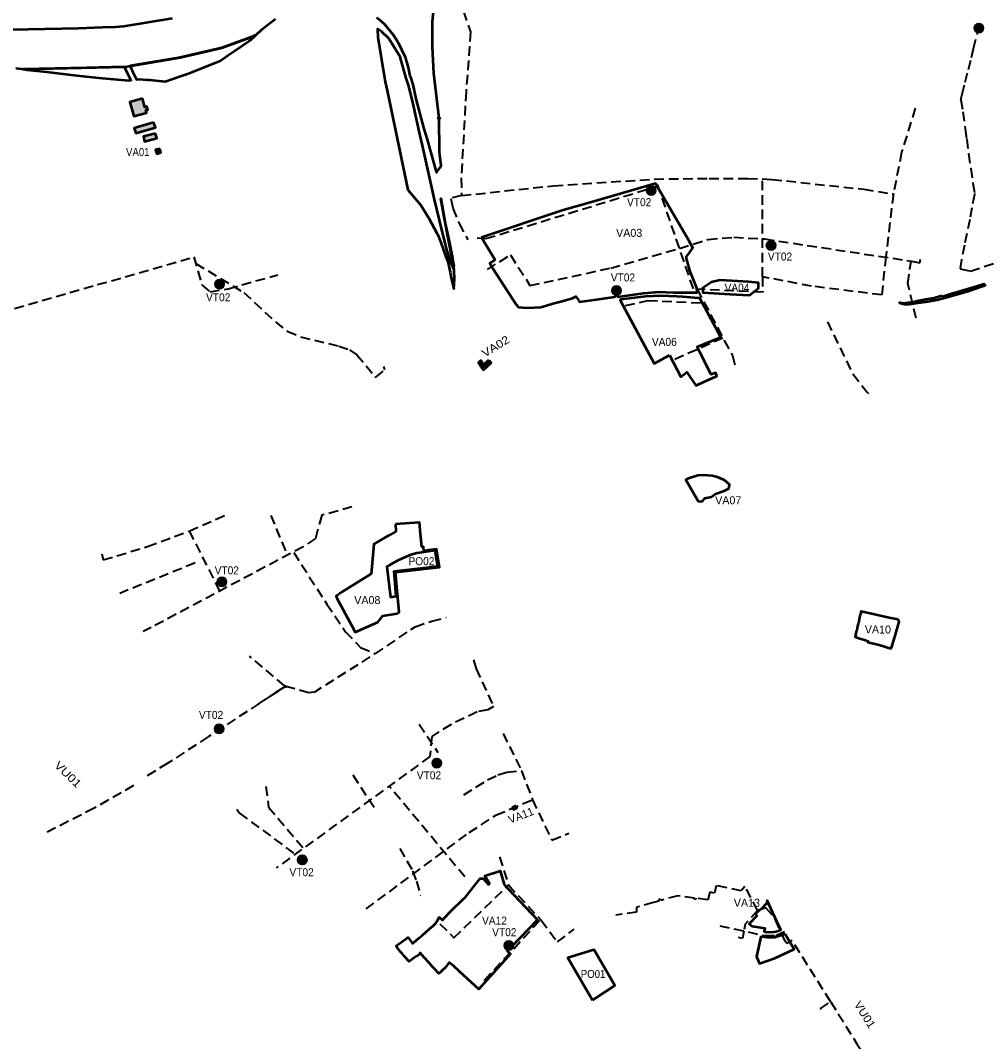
# Model space of a CAD drawing. Extents: x -650145 to -642675, y -1074338 to -1066724.
# Drawn here: x -648927 to -646512, y -1071699 to -1069147 of the extents above; entities that cross this region are included whole.
import ezdxf

# ---------------------------------------------------------------- set-up
doc = ezdxf.new("R2010")
doc.units = 0
doc.header["$LTSCALE"] = 8
doc.header["$PDMODE"] = 32
doc.header["$PDSIZE"] = 4
doc.linetypes.add('MEDIUM_DASHED', pattern=[4.5, 3, -1.5])
for name, color, linetype, lineweight in [('12', 7, 'MEDIUM_DASHED', 40), ('15', 7, 'Continuous', 13), ('44', 7, 'Continuous', 53), ('45', 7, 'Continuous', 53), ('46', 7, 'Continuous', 53), ('60', 7, 'Continuous', 53)]:
    doc.layers.add(name, color=color, linetype=linetype, lineweight=lineweight)
for name, color, linetype in [('17', 7, 'Continuous'), ('2', 7, 'Continuous'), ('3', 7, 'Continuous'), ('4', 7, 'Continuous'), ('5', 7, 'Continuous')]:
    doc.layers.add(name, color=color, linetype=linetype)

msp = doc.modelspace()

# ---------------------------------------------------------------- hatches: boundary and pattern name
at = {"layer": '15'}
for points in [[(-646519.621, -1069166.048, 1), (-646543.146, -1069166.048, 1)], [(-647338.289, -1069571.583, 1), (-647361.814, -1069571.583, 1)], [(-647038.994, -1069709.305, 1), (-647062.519, -1069709.305, 1)], [(-648416.978, -1069806.101, 1), (-648440.503, -1069806.101, 1)], [(-647425.058, -1069822.133, 1), (-647448.583, -1069822.133, 1)], [(-648411.342, -1070550.264, 1), (-648434.867, -1070550.264, 1)], [(-648418.374, -1070917.603, 1), (-648441.898, -1070917.603, 1)], [(-647874.426, -1071003.073, 1), (-647897.951, -1071003.073, 1)], [(-648210.363, -1071245, 1), (-648233.888, -1071245, 1)], [(-647694.212, -1071458.99, 1), (-647717.737, -1071458.99, 1)]]:
    msp.add_hatch(color=256, dxfattribs=at).paths.add_polyline_path(points)
at = {"layer": '60'}
for points in [[(-648621.37, -1069342.03), (-648652.93, -1069350.8), (-648642.85, -1069386.53), (-648611.53, -1069377.7), (-648613.3, -1069371.42), (-648608.07, -1069369.95), (-648610.3, -1069362.04), (-648615.51, -1069363.51)], [(-648593.77, -1069401.82), (-648642.06, -1069415.98), (-648638.41, -1069428.97), (-648589.26, -1069414.15), (-648592.11, -1069405.18)], [(-648589.16, -1069429.3), (-648619.35, -1069437.29), (-648616.15, -1069449.33), (-648585.96, -1069441.33)], [(-648578.5, -1069467.6), (-648588.59, -1069470.49), (-648585.91, -1069479.97), (-648575.76, -1069477.15)], [(-647753.96, -1069997.9), (-647755.37, -1069999.17), (-647757.35, -1069996.96), (-647768.87, -1070007.32), (-647775.67, -1069996.86), (-647781.47, -1070001.96), (-647774.7, -1070012.64), (-647775.34, -1070013.22), (-647769.35, -1070019.98), (-647749.87, -1070002.45)], [(-647687.68, -1071110.18), (-647696.64, -1071114.02), (-647694.63, -1071118.73), (-647685.66, -1071114.89)]]:
    msp.add_hatch(color=256, dxfattribs=at).paths.add_polyline_path(points)

# ---------------------------------------------------------------- linework, layer by layer
at = {"layer": '12'}
for p, q in [((-647072.241, -1069787.533), (-647072.241, -1069543.185)), ((-647291.307, -1069993.228), (-647170.84, -1069940.165)), ((-648300.887, -1070383.875), (-648259.756, -1070483.608)), ((-648504.855, -1070423.103), (-648428.725, -1070573.36)), ((-648490.212, -1070502.827), (-648678.059, -1070578.955)), ((-648332.818, -1070855.794), (-648263.929, -1070810.849)), ((-647929.7, -1070905.7), (-647883.483, -1070976.724)), ((-647720.463, -1070929.111), (-647674.039, -1071022.323)), ((-648042.555, -1071114.098), (-648099.428, -1071026.867)), ((-647815.949, -1071287.658), (-648004.905, -1071060.503)), ((-647767.223, -1071546.187), (-647626.359, -1071394.366))]:
    msp.add_line(p, q, dxfattribs=at)
for points in [[(-647819.537, -1069124.409), (-647801.818, -1069175.256), (-647812.644, -1069324.711), (-647825.015, -1069541.552), (-647823.978, -1069584.663), (-647594.109, -1069559.949), (-647342.265, -1069543.531), (-647205.182, -1069541.582), (-647108.806, -1069541.669), (-647047.983, -1069544.191), (-646818.857, -1069568.917), (-646744.903, -1069580.656), (-646763.998, -1069737.618), (-646773.775, -1069832.942), (-646949.668, -1069811.025), (-647072.241, -1069787.533), (-647071.353, -1069826.293), (-647244.785, -1069818.042), (-647338.767, -1069543.481)], [(-646576.25, -1069344.69), (-646576.07, -1069344.19), (-646572.92, -1069331.38), (-646565.43, -1069301.45), (-646557.53, -1069269.39), (-646550.09, -1069239.83), (-646544.34, -1069216.84), (-646534.934, -1069179.318)], [(-646576.25, -1069344.69), (-646576.14, -1069345.28), (-646571.6, -1069375.24), (-646565.13, -1069418.25), (-646561.67, -1069443.36), (-646557.02, -1069479.48), (-646551.76, -1069516.65), (-646546.19, -1069553.66), (-646542.189, -1069579.489), (-646541.86, -1069581.61), (-646548.99, -1069615.32), (-646554.11, -1069644.37), (-646561.65, -1069679.08), (-646567.03, -1069708.57), (-646575.01, -1069744.61), (-646578.22, -1069766.52), (-646578.238, -1069766.625), (-646578.433, -1069767.754), (-646552.777, -1069773.113), (-646552.12, -1069773.25), (-646464.51, -1069744.51)], [(-646690.349, -1069366.515), (-646724.478, -1069476.486), (-646744.903, -1069580.656)], [(-647785.07, -1069690.63), (-647763.238, -1069692.321), (-647332.905, -1069560.606)], [(-647823.978, -1069584.663), (-647851.235, -1069591.7), (-647845.629, -1069616.01), (-647830.41, -1069654.06), (-647808.595, -1069694.89)], [(-647279.5, -1069716.624), (-647208.318, -1069694.158), (-647143.504, -1069688.843), (-647066.866, -1069693.057), (-646699.975, -1069748.527), (-646678.869, -1069753.112), (-646676.91, -1069743.82)], [(-647759.613, -1069769.184), (-647701.982, -1069733.103), (-647653.087, -1069809.089), (-647451.321, -1069765.984), (-647279.5, -1069716.624)], [(-649044.908, -1069897.057), (-648493.206, -1069738.027), (-648473.126, -1069807.804), (-648452.457, -1069825.52), (-648407.58, -1069817.388), (-648283.564, -1069782.827)], [(-648488.496, -1069754.394), (-648368.286, -1069826.694), (-648289.499, -1069900.443), (-648259.719, -1069923.17), (-648226.806, -1069937.698), (-648130.85, -1069960.81), (-648103.867, -1069970.198), (-648085.696, -1069982.585), (-648038.819, -1070039.248), (-648015.643, -1070020.009), (-648018.277, -1070012.103)], [(-646687.702, -1069891.186), (-646709.186, -1069804.667), (-646700.4, -1069748.435)], [(-647235.467, -1069818.485), (-647167.428, -1069946.59), (-647147.296, -1069984.626), (-647140.3, -1070010.7)], [(-647414.535, -1069859.089), (-647358.559, -1069846.998), (-647217.195, -1069852.888)], [(-646909.766, -1069900.481), (-646846.095, -1070030.546), (-646811.614, -1070075.327), (-646807.189, -1070079.418)], [(-648723.27, -1070480.1), (-648719.781, -1070495.186), (-648608.642, -1070462.104), (-648504.855, -1070423.103), (-648414.278, -1070383.546)], [(-648097.961, -1070362.859), (-648173.666, -1070383.828), (-648189.212, -1070442.001), (-648219.63, -1070462.294), (-648600.13, -1070664.406), (-648620.205, -1070674.13)], [(-648243.287, -1070476.499), (-648161.107, -1070605.619), (-648114.121, -1070674.786), (-648076.532, -1070713.851), (-648039.863, -1070730.017), (-647940.305, -1070662.397), (-647898.38, -1070648.071), (-647862.25, -1070638.96)], [(-648053, -1070737.9), (-648191.415, -1070825.487), (-648206.369, -1070827.623), (-648259.779, -1070812.134), (-648269.723, -1070814.735), (-648457.192, -1070937.393), (-648558.532, -1071003.71), (-648610.798, -1071035.598)], [(-648259.67, -1070812.106), (-648266.577, -1070810.067), (-648354.282, -1070735.576)], [(-647794.16, -1070745.19), (-647787.83, -1070767.157), (-647743.987, -1070862.016), (-647758.284, -1070869.702), (-647784.836, -1070875.103), (-647850.393, -1070906.456), (-647898.698, -1070936.31), (-647903.521, -1070987.043), (-648287.54, -1071265.293)], [(-647818.707, -1071082.607), (-647759.543, -1071045.17), (-647733.735, -1071032.504), (-647710.774, -1071025.971), (-647674.039, -1071022.323), (-647646.98, -1071094.735)], [(-648643.705, -1071059.314), (-648742.207, -1071116.062), (-648865.074, -1071178.477)], [(-648313.283, -1071061.443), (-648306.336, -1071112.945), (-648219.799, -1071215.376)], [(-648062.403, -1071367.342), (-647805.426, -1071176.999), (-647738.219, -1071133.017), (-647646.98, -1071094.735), (-647598.326, -1071195.826), (-647556.251, -1071178.604)], [(-648386.1, -1071118.4), (-648378.803, -1071128.097), (-648240.257, -1071231.033)], [(-647978.731, -1071216.254), (-647946.561, -1071272.093), (-647936.852, -1071298.253), (-647926.931, -1071334.225)], [(-647728.988, -1071237.115), (-647707.004, -1071307.776), (-647625.351, -1071395.71), (-647584.501, -1071450.177), (-647542.285, -1071418.425)], [(-647878.3, -1071404.7), (-647843.135, -1071439.808), (-647707.004, -1071307.776)], [(-647125.34, -1071322.14), (-647187.77, -1071309.47), (-647192.05, -1071327.84), (-647204.02, -1071325.39), (-647208.89, -1071345.24), (-647238.16, -1071341.03), (-647238.54, -1071343.71), (-647242.66, -1071343.12), (-647242.27, -1071340.44), (-647283.52, -1071334.51), (-647326.47, -1071346.51), (-647327.32, -1071343.47), (-647332.03, -1071344.79), (-647331.18, -1071347.82), (-647344.33, -1071351.49)], [(-647084.37, -1071371.2), (-647115.91, -1071311.35), (-647125.34, -1071322.14)], [(-647344.33, -1071351.49), (-647386.85, -1071363.37), (-647386.8, -1071375.58), (-647438.34, -1071382.93)], [(-647084.37, -1071371.2), (-647115.19, -1071405.75), (-647117.79, -1071418.96)], [(-646901.7, -1071599.29), (-646997.62, -1071446.82), (-647011, -1071454.09), (-647015.17, -1071448), (-647045.84, -1071382.28), (-647050.73, -1071380.13), (-647063.41, -1071364.59), (-647084.37, -1071371.2)], [(-647178.442, -1071409.986), (-647065.935, -1071434.456), (-647038.805, -1071433.925), (-647016.651, -1071423.819)], [(-647118.63, -1071423.24), (-647122.21, -1071441.39), (-647132.07, -1071439.37)], [(-646925.38, -1071619.26), (-646926.8, -1071616.72), (-646901.7, -1071599.29)], [(-646901.7, -1071599.29), (-646836.01, -1071704.74), (-646804.94, -1071754.31)]]:
    msp.add_lwpolyline(points, dxfattribs=at)
at = {"layer": '15', "lineweight": 35}
for centre in [(-646531.383, -1069166.048), (-647350.051, -1069571.583), (-647050.756, -1069709.305), (-648428.74, -1069806.101), (-647436.82, -1069822.133), (-648423.104, -1070550.264), (-648430.136, -1070917.603), (-647886.188, -1071003.073), (-648222.125, -1071245), (-647705.974, -1071458.99)]:
    msp.add_circle(centre, 11.762, dxfattribs=at)
at = {"layer": '44'}
for p, q in [((-647862.266, -1069668.613), (-647843.449, -1069768.252)), ((-646729.54, -1069853.69), (-646729.24, -1069851.41))]:
    msp.add_line(p, q, dxfattribs=at)
for points in [[(-647893.553, -1069279.017), (-647896.67, -1069213.573), (-647896.362, -1069149.171), (-647886.615, -1069053.052)], [(-648036.291, -1069139.458), (-648031.92, -1069142.67), (-648016.36, -1069156.54), (-647993.8, -1069184.11)], [(-648526.15, -1069286.21), (-648508.95, -1069280.01), (-648427.08, -1069247.75), (-648407.73, -1069233.88), (-648389.91, -1069221.86), (-648355.81, -1069198.88), (-648351.77, -1069195.88), (-648338.523, -1069183.389), (-648354.978, -1069190.492)], [(-648005.47, -1069192.09), (-648024.02, -1069174.7), (-648034.421, -1069167.61)], [(-648034.421, -1069167.61), (-648034.421, -1069167.61), (-648033, -1069189), (-648015, -1069300), (-648010.092, -1069322.087), (-647980.331, -1069465.915), (-647958.34, -1069570.699), (-647925.99, -1069608.57), (-647906.16, -1069641.48), (-647885.665, -1069678.788), (-647885.663, -1069678.794), (-647883.51, -1069682.71), (-647875.82, -1069701.85), (-647875.82, -1069701.85), (-647864.19, -1069735.12), (-647858.44, -1069749.43), (-647852.63, -1069775.7), (-647850.66, -1069785.74), (-647849.165, -1069793.367)], [(-647993.8, -1069184.11), (-647982.58, -1069202.33), (-647965.06, -1069238.95), (-647957.56, -1069264.74), (-647953.01, -1069285.73), (-647951.841, -1069289.09)], [(-648354.978, -1069190.492), (-648423.173, -1069215.44), (-648527.693, -1069239.938), (-648652.716, -1069260.657), (-648647.059, -1069272.723), (-648636.85, -1069294.49), (-648630.82, -1069293.63), (-648609.425, -1069295.033), (-648603.228, -1069295.53), (-648565.18, -1069299.46), (-648526.15, -1069286.21)], [(-647962.2, -1069290.88), (-647974.81, -1069246.86), (-647977.29, -1069238.21), (-648005.47, -1069192.09)], [(-647880.318, -1069391.297), (-647880.326, -1069390.832), (-647893.553, -1069279.017)], [(-647852.78, -1069745.71), (-647859.722, -1069722.428), (-647872.87, -1069673.56), (-647892.79, -1069591.06), (-647892.789, -1069591.06), (-647893.75, -1069587.08), (-647922.04, -1069459.71), (-647925.16, -1069445.68), (-647928.41, -1069431.03), (-647945.28, -1069355.1), (-647956.27, -1069311.58), (-647962.2, -1069290.88)], [(-647951.841, -1069289.09), (-647945.63, -1069306.95), (-647938.77, -1069343.17), (-647918.08, -1069417.43), (-647909.67, -1069444.46), (-647889.22, -1069519.32), (-647887.087, -1069527.229), (-647885.782, -1069525.389), (-647882.551, -1069520.835), (-647878.73, -1069515.45)], [(-647878.73, -1069515.45), (-647874.75, -1069509.84), (-647878.93, -1069475.09), (-647880.318, -1069391.297)], [(-647843.449, -1069768.252), (-647844.371, -1069761.991), (-647842.438, -1069760.647), (-647845.086, -1069748.753), (-647846.484, -1069736.663), (-647855.158, -1069695.232), (-647865.69, -1069647.32), (-647876.061, -1069592.206), (-647862.266, -1069668.613)], [(-647841.402, -1069792.351), (-647842.489, -1069773.282), (-647842.622, -1069770.956), (-647843.337, -1069769.013), (-647843.443, -1069768.293), (-647852.78, -1069745.71)], [(-647849.165, -1069793.367), (-647843.74, -1069817.63), (-647841.402, -1069792.351)], [(-646515.63, -1069810.24), (-646522.32, -1069812.28), (-646560.92, -1069825.33), (-646613.65, -1069840.02), (-646620.06, -1069841.69), (-646629.83, -1069844.23), (-646635.93, -1069845.82), (-646658.5, -1069850.59), (-646689.73, -1069854.58), (-646705.87, -1069856.62), (-646717.66, -1069857.11), (-646729.54, -1069853.69)], [(-646593.34, -1069827.68), (-646518.19, -1069805.27), (-646515.63, -1069810.24)], [(-646729.24, -1069851.41), (-646723.5, -1069852.83), (-646719.82, -1069853.78), (-646689.63, -1069849.7), (-646689.8, -1069848.71), (-646664.22, -1069843.72), (-646648.18, -1069841.04), (-646648.28, -1069841.78), (-646638.34, -1069838.73), (-646623.31, -1069834.1)], [(-646623.31, -1069834.1), (-646622.54, -1069835.88), (-646622.19, -1069836.71), (-646597.29, -1069828.86), (-646593.34, -1069827.68)]]:
    msp.add_lwpolyline(points, dxfattribs=at)
msp.add_lwpolyline([(-648730.66, -1069290.43), (-648655.53, -1069297.18), (-648650.06, -1069296.39), (-648650.58, -1069295.34), (-648662.417, -1069271.858), (-648666.827, -1069262.738), (-648761.189, -1069265.035), (-648918.889, -1069268.875), (-648909.86, -1069270.02), (-648861.49, -1069275.34), (-648785.92, -1069284.2), (-648730.66, -1069290.43)], close=True, dxfattribs=at)
msp.add_arc((-648354.978, -1069190.492), 0.000000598, 264.13978, 298.69712, dxfattribs=at)
msp.add_point((-647880.318, -1069391.297), dxfattribs=at)
at = {"layer": '45'}
for points in [[(-648547.243, -1069141.81), (-648668.959, -1069161.838), (-648688.912, -1069163.603), (-648721.315, -1069164.952), (-648781.015, -1069167.44), (-649076.02, -1069172.683)], [(-648937.91, -1069266.51), (-648924.13, -1069268.21), (-648918.889, -1069268.875), (-648665.007, -1069262.694), (-648527.693, -1069239.938), (-648423.173, -1069215.44), (-648354.978, -1069190.492), (-648338.523, -1069183.389), (-648322.14, -1069168.56), (-648306.83, -1069156.57), (-648289.25, -1069142.79)]]:
    msp.add_lwpolyline(points, dxfattribs=at)
at = {"layer": '46'}
for points in [[(-647883.383, -1070511.163), (-647889.978, -1070472.005), (-647936.144, -1070478.187), (-647950.48, -1070482.79), (-647962.184, -1070487.748), (-647981.81, -1070496.06), (-647999.756, -1070505.655), (-648010.831, -1070512.588), (-648002, -1070588), (-647987.667, -1070585.565), (-647992.819, -1070523.117)], [(-647497.04, -1071595.66), (-647440.67, -1071558.93), (-647492.3, -1071470), (-647495.85, -1071471.06), (-647558.654, -1071489.738)]]:
    msp.add_lwpolyline(points, close=True, dxfattribs=at)
at = {"layer": '60'}
for points in [[(-648621.37, -1069342.03), (-648652.93, -1069350.8), (-648642.85, -1069386.53), (-648611.53, -1069377.7), (-648613.3, -1069371.42), (-648608.07, -1069369.95), (-648610.3, -1069362.04), (-648615.51, -1069363.51)], [(-648593.77, -1069401.82), (-648642.06, -1069415.98), (-648638.41, -1069428.97), (-648589.26, -1069414.15), (-648592.11, -1069405.18)], [(-648589.16, -1069429.3), (-648619.35, -1069437.29), (-648616.15, -1069449.33), (-648585.96, -1069441.33)], [(-648578.5, -1069467.6), (-648588.59, -1069470.49), (-648585.91, -1069479.97), (-648575.76, -1069477.15)], [(-647774.11, -1069689.64), (-647740.74, -1069744.24), (-647742.36, -1069746.93), (-647753.7, -1069753.9), (-647745.84, -1069766.71), (-647687.45, -1069857.15), (-647681.51, -1069863.72), (-647661.79, -1069864.92), (-647641.78, -1069864.26), (-647625.83, -1069863.19), (-647593.07, -1069853.74), (-647572.63, -1069848.63), (-647547.12, -1069840.87), (-647538.34, -1069836.68), (-647531.33, -1069847.23), (-647529.5, -1069849.99), (-647492.76, -1069845.02), (-647441.19, -1069837.6), (-647437.46, -1069832.27), (-647433.32, -1069837.33), (-647369.3, -1069828.22), (-647330.46, -1069825.51), (-647294.38, -1069826.88), (-647270.09, -1069827.02), (-647253.88, -1069827.12), (-647236.5, -1069826.63), (-647235.49, -1069826.51), (-647235.62, -1069817.62), (-647253.45, -1069771.95), (-647262.46, -1069738.25), (-647253.97, -1069726.27), (-647247.86, -1069717.66), (-647246.42, -1069715.63), (-647256.061, -1069697.32), (-647339.58, -1069554.46), (-647375.71, -1069564.91), (-647499.63, -1069600.73), (-647570.37, -1069621.18)], [(-647178.73, -1069796.4), (-647199.65, -1069800.69), (-647221.87, -1069816.21), (-647221.14, -1069826.761), (-647153.36, -1069830.79), (-647104.741, -1069833.568), (-647082.145, -1069816.321), (-647082.206, -1069802.916), (-647107.04, -1069799.84), (-647148.9, -1069797.88)], [(-647304.05, -1069983.79), (-647294.257, -1070002.745), (-647276, -1070038.08), (-647261.27, -1070026.12), (-647238.99, -1070059.05), (-647195.933, -1070040.107), (-647186.148, -1070035.802), (-647186.4, -1070035.27), (-647189.83, -1070027.59), (-647199.984, -1070032.112), (-647229.096, -1069974.658), (-647235, -1069963), (-647176.499, -1069938.333), (-647217.177, -1069862.57), (-647228.77, -1069840.98), (-647232.66, -1069841.07), (-647270.71, -1069837.61), (-647285.9, -1069836.66), (-647326.71, -1069835.46), (-647363.21, -1069836.64), (-647425.73, -1069844.31), (-647427.62, -1069845.94), (-647413.461, -1069872.442), (-647342.93, -1070004.49)], [(-647753.96, -1069997.9), (-647755.37, -1069999.17), (-647757.35, -1069996.96), (-647768.87, -1070007.32), (-647775.67, -1069996.86), (-647781.47, -1070001.96), (-647774.7, -1070012.64), (-647775.34, -1070013.22), (-647769.35, -1070019.98), (-647749.87, -1070002.45)], [(-647219.36, -1070283.36), (-647233.82, -1070284.22), (-647259.22, -1070292.91), (-647263.72, -1070295.43), (-647232.55, -1070348.65), (-647226.24, -1070348.88), (-647220.9, -1070348.04), (-647216.16, -1070340.99), (-647199.79, -1070337.21), (-647189.63, -1070330.53), (-647167.43, -1070322.66), (-647155.89, -1070316.51), (-647154.23, -1070306.63), (-647167.15, -1070295.69), (-647184.77, -1070288.73), (-647197.68, -1070285.3)], [(-647988.86, -1070405.95), (-647988.11, -1070423.93), (-648005.668, -1070434.145), (-648014.63, -1070439.36), (-648043.43, -1070456.12), (-648050.38, -1070530.2), (-648122.57, -1070575), (-648137.78, -1070586.25), (-648135.47, -1070590.61), (-648098.637, -1070659.682), (-648089.82, -1070676.22), (-648033.29, -1070651.18), (-648020.51, -1070635.05), (-647985.44, -1070629.07), (-647980.2, -1070625.7), (-647989.5, -1070525.73), (-647901.695, -1070516.259), (-647879.16, -1070513.83), (-647887.08, -1070468.54), (-647917.98, -1070472.47), (-647918.95, -1070462.36), (-647923.53, -1070462.75), (-647926.53, -1070429.76), (-647929.24, -1070401.97)], [(-646825.54, -1070624.03), (-646826.12, -1070623.9), (-646826.45, -1070627.3), (-646827.98, -1070632.83), (-646828.22, -1070632.77), (-646829.55, -1070638.78), (-646829.55, -1070638.78), (-646829.3, -1070638.83), (-646830.51, -1070644.3), (-646830.26, -1070644.35), (-646832.46, -1070654.31), (-646832.7, -1070654.26), (-646834.27, -1070661.39), (-646834.27, -1070661.39), (-646834.4, -1070661.35), (-646835.23, -1070665.08), (-646835.1, -1070665.12), (-646836.6, -1070671.54), (-646836.6, -1070671.54), (-646836.87, -1070671.46), (-646839.27, -1070681.62), (-646838.96, -1070681.72), (-646840.36, -1070687.86), (-646828.7, -1070691.73), (-646816.84, -1070695.43), (-646808.09, -1070698.19), (-646808.76, -1070701.11), (-646780.44, -1070707.59), (-646751.23, -1070717), (-646748.04, -1070709.23), (-646741.52, -1070687.22), (-646730.66, -1070650.07), (-646734.18, -1070644.6), (-646755.21, -1070639.87), (-646755.84, -1070639.88), (-646784.62, -1070633.19)], [(-647687.68, -1071110.18), (-647696.64, -1071114.02), (-647694.63, -1071118.73), (-647685.66, -1071114.89)], [(-647777.4, -1071291.32), (-647777.4, -1071291.32), (-647774.14, -1071291.34), (-647769.85, -1071291.91), (-647756.67, -1071306.77), (-647753.89, -1071303.94), (-647766.35, -1071285.11), (-647727.368, -1071272.362), (-647717.363, -1071306.29), (-647708.429, -1071316.821), (-647634.524, -1071394.901), (-647700.078, -1071462.96), (-647710.546, -1071472.023), (-647704.78, -1071477.1), (-647701.415, -1071480.15), (-647708.18, -1071487.57), (-647767.575, -1071553.083), (-647781.31, -1071567.79), (-647789.73, -1071560.1), (-647828.024, -1071525.256), (-647844.4, -1071510.2), (-647850.55, -1071505.14), (-647855.23, -1071501.297), (-647860.576, -1071508.843), (-647864.69, -1071514.65), (-647869.922, -1071519.269), (-647876.29, -1071524.89), (-647881.16, -1071529.25), (-647883.31, -1071526.83), (-647889.29, -1071520.11), (-647897.27, -1071511.15), (-647905.25, -1071502.19), (-647917.23, -1071488.75), (-647927.2, -1071477.54), (-647929.26, -1071480.77), (-647931.17, -1071482.12), (-647936.59, -1071485.96), (-647944.81, -1071491.78), (-647955.14, -1071499.23), (-647967.13, -1071486.01), (-647972.76, -1071479), (-647977.13, -1071474.05), (-647984.07, -1071465.1), (-647987.8, -1071459.68), (-647961.4, -1071441.47), (-647957.906, -1071439.06), (-647946.78, -1071454.23), (-647937.43, -1071446.16), (-647930.38, -1071440.08), (-647921.96, -1071432.81), (-647913.31, -1071425.35), (-647904.3, -1071417.58), (-647895.29, -1071409.81), (-647888.11, -1071403.61), (-647885.05, -1071397.88), (-647879.76, -1071387.96), (-647871.68, -1071395.59), (-647867.45, -1071390.95), (-647849.86, -1071372.18), (-647820.93, -1071344.25), (-647815.474, -1071339.22)], [(-647056.48, -1071355.32), (-647060.6, -1071346.87), (-647060.22, -1071349.87), (-647061.4, -1071352.51), (-647062.78, -1071354.77), (-647073.68, -1071366.75), (-647075.25, -1071368.01), (-647083.48, -1071374.62), (-647090.04, -1071379.44), (-647088.57, -1071381.97), (-647086.45, -1071384.59), (-647105.2, -1071404.54), (-647097.5, -1071410.96), (-647066.35, -1071415.79), (-647068.162, -1071424.298), (-647061.23, -1071425.434), (-647043.137, -1071424.978), (-647038.119, -1071424.37), (-647026.472, -1071419.614), (-647035.47, -1071400.31)], [(-647015.484, -1071430.864), (-647040.878, -1071438.769), (-647060.532, -1071439.002), (-647076.037, -1071437.073), (-647086.716, -1071486.782), (-647079.168, -1071503.954), (-647040.889, -1071490.395), (-646992.555, -1071467.975)]]:
    msp.add_lwpolyline(points, close=True, dxfattribs=at)

# ---------------------------------------------------------------- texts
at = {"layer": '17', "width": 0.95}
for p in [(-647410.59, -1069611.16), (-647058.579, -1069746.971), (-647451.166, -1069799.33), (-648462.628, -1069848.885), (-648441.04, -1070531.428), (-648480.548, -1070892.65), (-647935.934, -1071043.636), (-648254.236, -1071285.892), (-647747.641, -1071435.784)]:
    msp.add_text('VT02', height=20, dxfattribs=at).set_placement(p)
at = {"layer": '2'}
for rotation, width, p in [(315.876, 1.2, (-648843.543, -1071010.613)), (302.088, 1.1, (-646844.301, -1071605.934))]:
    msp.add_text('VU01', height=20, rotation=rotation, dxfattribs=dict(at, width=width)).set_placement(p)
at = {"layer": '3'}
for s, width, p in [('VA01', 0.9, (-648662.691, -1069485.662)), ('VA04', 0.95, (-647166.855, -1069824.823)), ('VA06', 0.95, (-647348.354, -1069960.268)), ('VA12', 0.95, (-647772.908, -1071406.958))]:
    msp.add_text(s, height=20, dxfattribs=dict(at, width=width)).set_placement(p)
for s, p in [('VA03', (-647437.904, -1069687.886)), ('VA07', (-647190.33, -1070356.214)), ('VA08', (-648092.311, -1070605.712)), ('VA13', (-647143.769, -1071362.286))]:
    msp.add_text(s, height=20, dxfattribs=at).set_placement(p)
at = {"layer": '3', "width": 1.15}
msp.add_text('VA02', height=20, rotation=31.795, dxfattribs=at).set_placement((-647765.887, -1069989.737))
at = {"layer": '3'}
for s, rotation, p in [('VA10', 359.629, (-646816.427, -1070678.964)), ('VA11', 20.894, (-647702.554, -1071154.847))]:
    msp.add_text(s, height=20, rotation=rotation, dxfattribs=at).set_placement(p)
at = {"layer": '4', "width": 0.9}
msp.add_text('PO01', height=20, dxfattribs=at).set_placement((-647526.167, -1071540.041))
at = {"layer": '5', "width": 0.95}
msp.add_text('PO02', height=20, dxfattribs=at).set_placement((-647956.859, -1070508.429))

doc.saveas('drawing.dxf')
